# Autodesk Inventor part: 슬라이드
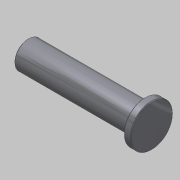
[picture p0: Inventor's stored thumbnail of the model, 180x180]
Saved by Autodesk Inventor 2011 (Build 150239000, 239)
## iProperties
Created: 2013-06
Part Number: 슬라이드
Document SubType Name: Modeling
Designer: SeoGD™[esajin.kr]
Density: 1 g/cm^3
Mass: 203.978 g
Surface Area: 269.019 cm^2
Volume: 203.978 cm^3
Author: SeoGD™[esajin.kr]
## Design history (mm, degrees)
sketch "스케치1"
  geometry: L1 (-75, 162)-(-75, 58) reference; L2 (-148, 110)-(22, 110); L3 (-148, 110)-(-148, 129); L4 (-148, 129)-(12, 129); L5 (12, 129)-(12, 139); L6 (12, 139)-(22, 139); L7 (22, 139)-(22, 110); 2 further points
  constraints: 12 end point, 3 parallel, 3 perpendicular, 1 midpoint, 1 point on line
  dimensions: "d0" = 58 diameter of L6 L2; "d1" = 38 diameter of L4 L2; "d2" = 10 distance of L5.end L6.end; "d3" = 170 distance of L2.start L2.end; "d4" = 73 distance between parallel lines of L3 L1
revolve "회전1" sketch "스케치1" stored, may be unused: angle "d5" = 90 deg
hole "구멍1" diameter "d11" = 13.376; stored, may be unused: countersink angle "d15" = 90 deg, drill point angle "d17" = 118 deg; dims "d9" = 10, "d10" = 10, "d12" = 22, "d13" = 4, "d14" = 2, "d16" = 25
chamfer "모따기1" distance "d6" = 1; stored, may be unused: second distance "d7" = 2, angle "d8" = 45 deg
node "솔리드1"
node "참조1"
